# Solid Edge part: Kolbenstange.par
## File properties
Username: bmolnar
Dokumentum tartalom típus: 0
Author: bmolnar
Last saved by: bmolnar
Revision: 97
Sűrűség: 0,000 kg/m^3
Pontosság: 0,990
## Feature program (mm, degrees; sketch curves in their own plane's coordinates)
base feature "unnamed BaseFeature 1"
thread "unnamed Thread 1"
chamfer "Letörés_1"  SetBackValue2 = 20 deg
sketch used by "Kihúzás_1" plane through (0, 0, -24) normal (0, 0, -1) x-axis (-1, 0, 0)
extrude "Kihúzás_1" add finite 12.4 along +normal
sketch for "Kihúzás_2" plane through (0, 0, -24) normal (0, 0, -1) x-axis (-1, 0, 0)
extrude "Kihúzás_2" add finite 3.4 along -normal
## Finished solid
Body 1: solid body, 17 faces, 23 edges, 8 vertices.
  Faces by surface: plane 8, cylinder 4, torus 3, cone 2
  Edges by curve: circle 13, line 6, ellipse 2, intersection 2
Bounding box of the edges (mm; curved faces can reach further): 32.000 x 32.000 x 375.400, from (-16, -16, -36.4) to (16, 16, 339).
Cylindrical faces by radius (mm): R3.95 x1, R5 x1, R6 x1, R16 x1
Conical faces (half-angle, radius in mm at the cone's reference point): 20 deg R3.9991 x1, 60 deg R4.575 x1
Toroidal faces (ring radius, tube radius in mm): R4.35 r0.4 x2, R4.8 r1.2 x1
Planar faces by outward normal: +x 1, +z 3, -x 1, -z 1, oblique 2
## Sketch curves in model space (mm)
circle centre (0, 0, -24) radius 16
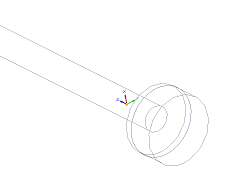
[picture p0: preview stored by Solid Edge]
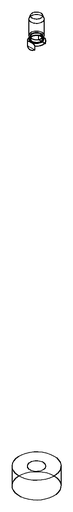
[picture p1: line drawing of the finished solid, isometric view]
